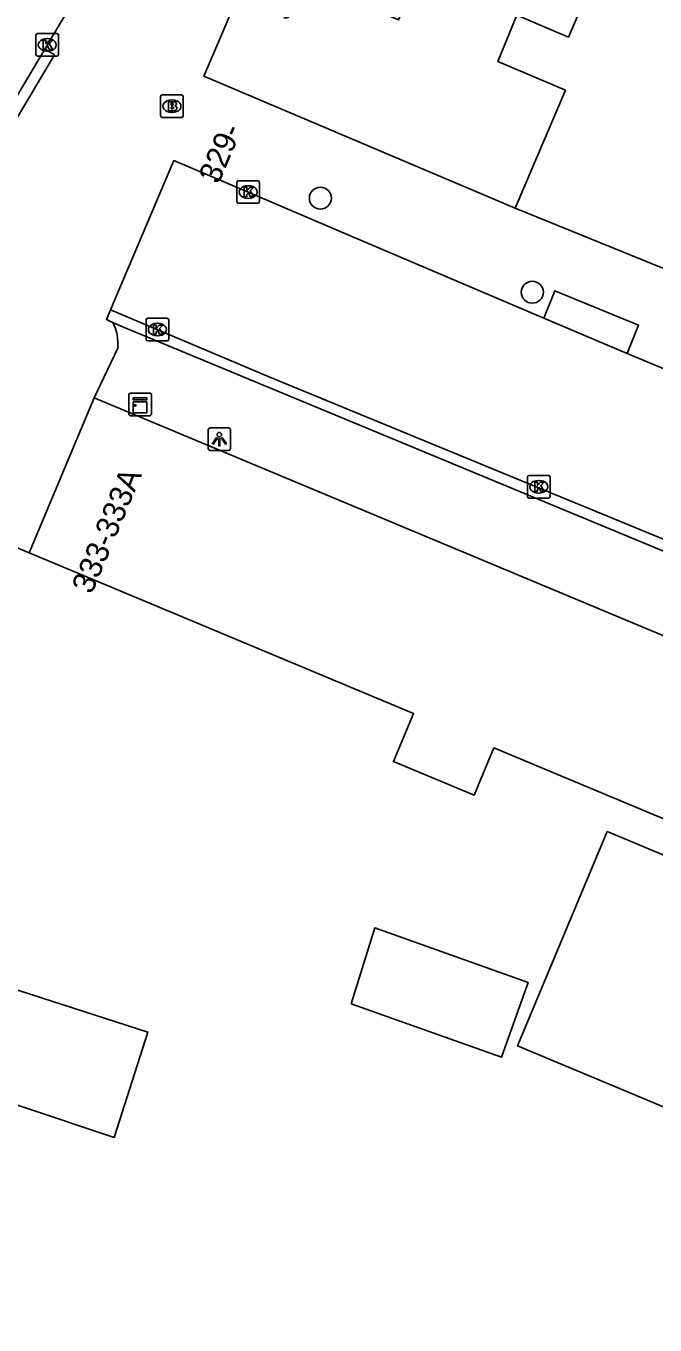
# Model space of a CAD drawing. Extents: x 160557 to 161245, y 385330 to 386505.
# Drawn here: x 160889.6 to 160917.5, y 385811 to 385868.6 of the extents above; entities that cross this region are included whole.
import ezdxf

# ---------------------------------------------------------------- set-up
doc = ezdxf.new("R2010")
doc.units = 0
for name, color, linetype in [('IMGEO_Boom', 7, 'Continuous'), ('IMGEO_Brandkraan', 7, 'Continuous'), ('IMGEO_Kast', 7, 'Continuous'), ('IMGEO_Kolk', 7, 'Continuous'), ('IMGEO_Lichtpunt', 7, 'Continuous'), ('IMGEO_Pand', 7, 'Continuous'), ('IMGEO_Pand_nummerreeks', 7, 'Continuous'), ('IMGEO_Rijbaan_lokaal_gesloten', 7, 'Continuous'), ('IMGEO_Rijbaan_lokaal_open', 7, 'Continuous'), ('IMGEO_Voetpad_open', 7, 'Continuous')]:
    doc.layers.add(name, color=color, linetype=linetype)

msp = doc.modelspace()

# ---------------------------------------------------------------- linework, layer by layer
at = {"layer": 'IMGEO_Boom'}
for centre in [(160902.686, 385860.988), (160912.08, 385856.817)]:
    msp.add_circle(centre, 0.489, dxfattribs=at)
at = {"layer": 'IMGEO_Brandkraan'}
for p, q in [((160895.602, 385864.643), (160895.602, 385865.495)), ((160895.677, 385865.569), (160896.529, 385865.569)), ((160896.603, 385865.495), (160896.603, 385864.643)), ((160896.09, 385865.349), (160896.115, 385865.349)), ((160896.529, 385864.569), (160895.677, 385864.569)), ((160896.113, 385864.789), (160896.088, 385864.789))]:
    msp.add_line(p, q, dxfattribs=at)
for points in [[(160895.602, 385864.643), (160895.602, 385865.495)], [(160895.677, 385865.569), (160896.529, 385865.569)], [(160896.603, 385865.495), (160896.603, 385864.643)], [(160895.95, 385865.269), (160895.95, 385864.869), (160896.163, 385864.869)], [(160896.181, 385865.269), (160895.95, 385865.269)], [(160896.129, 385865.188), (160896.075, 385865.188), (160896.075, 385865.112)], [(160896.075, 385865.112), (160896.128, 385865.112)], [(160896.137, 385865.036), (160896.075, 385865.036), (160896.075, 385864.955)], [(160896.075, 385864.955), (160896.137, 385864.955)], [(160896.529, 385864.569), (160895.677, 385864.569)]]:
    msp.add_lwpolyline(points, dxfattribs=at)
for centre, radius, start, end in [((160895.679, 385865.493), 0.0765, 91.55205, 178.44795), ((160895.679, 385865.493), 0.0765, 91.55205, 178.44795), ((160896.527, 385865.493), 0.0765, 1.55205, 88.44795), ((160896.527, 385865.493), 0.0765, 1.55205, 88.44795), ((160896.13, 385865.15), 0.0379, 267.82845, 90.93552), ((160896.138, 385864.995), 0.0404, 269.87594, 90.50774), ((160896.169, 385865.12), 0.251, 268.66757, 293.53466), ((160896.185, 385865.124), 0.145, 59.4692, 91.53667), ((160896.21, 385865.171), 0.0922, 285.51372, 58.15012), ((160896.215, 385864.979), 0.105, 301.31148, 78.98903), ((160895.679, 385864.645), 0.0765, 181.55205, 268.44795), ((160895.679, 385864.645), 0.0765, 181.55205, 268.44795), ((160896.527, 385864.645), 0.0765, 271.55205, 358.44795), ((160896.527, 385864.645), 0.0765, 271.55205, 358.44795)]:
    msp.add_arc(centre, radius, start, end, dxfattribs=at)
for centre, major_axis, ratio, start_param, end_param in [((160896.089, 385865.069), (-0.387, 0.002), 0.722429, 4.712389, 7.853982), ((160896.114, 385865.069), (-0.39, 0.002), 0.717154, 1.570796, 4.712389)]:
    msp.add_ellipse(centre, major_axis=major_axis, ratio=ratio, start_param=start_param, end_param=end_param, dxfattribs=at)
at = {"layer": 'IMGEO_Kast'}
for p, q in [((160894.194, 385851.411), (160894.194, 385852.252)), ((160894.194, 385852.252), (160894.194, 385851.411)), ((160894.269, 385852.336), (160895.11, 385852.336)), ((160895.11, 385852.336), (160894.269, 385852.336)), ((160895.194, 385852.261), (160895.194, 385851.42)), ((160895.194, 385851.42), (160895.194, 385852.261)), ((160895.119, 385851.336), (160894.278, 385851.336)), ((160894.278, 385851.336), (160895.119, 385851.336))]:
    msp.add_line(p, q, dxfattribs=at)
for points in [[(160894.389, 385852.126), (160894.989, 385852.126), (160894.989, 385852.041), (160894.389, 385852.041), (160894.389, 385852.126)], [(160894.389, 385851.951), (160894.989, 385851.951), (160894.989, 385851.462), (160894.389, 385851.462), (160894.389, 385851.951)]]:
    msp.add_lwpolyline(points, dxfattribs=at)
msp.add_circle((160894.473, 385851.8), 0.0377, dxfattribs=at)
for centre, start, end in [((160894.272, 385852.258), 92.4484, 184.28452), ((160894.272, 385852.258), 92.4484, 184.28452), ((160895.116, 385852.258), 2.4484, 94.28452), ((160895.116, 385852.258), 2.4484, 94.28452), ((160894.272, 385851.414), 182.4484, 274.28452), ((160894.272, 385851.414), 182.4484, 274.28452), ((160895.116, 385851.414), 272.4484, 4.28452), ((160895.116, 385851.414), 272.4484, 4.28452)]:
    msp.add_arc(centre, 0.0779, start, end, dxfattribs=at)
at = {"layer": 'IMGEO_Kolk'}
for p, q in [((160890.074, 385867.362), (160890.074, 385868.214)), ((160890.149, 385868.288), (160891.001, 385868.288)), ((160890.562, 385868.068), (160890.587, 385868.068)), ((160891.075, 385868.214), (160891.075, 385867.362)), ((160891.001, 385867.288), (160890.149, 385867.288)), ((160890.585, 385867.508), (160890.56, 385867.508)), ((160898.983, 385860.834), (160898.983, 385861.686)), ((160899.058, 385861.76), (160899.91, 385861.76)), ((160899.471, 385861.54), (160899.496, 385861.54)), ((160899.984, 385861.686), (160899.984, 385860.834)), ((160899.494, 385860.98), (160899.469, 385860.98)), ((160899.91, 385860.76), (160899.058, 385860.76)), ((160894.958, 385854.733), (160894.958, 385855.585)), ((160895.033, 385855.659), (160895.885, 385855.659)), ((160895.446, 385855.439), (160895.471, 385855.439)), ((160895.959, 385855.585), (160895.959, 385854.733)), ((160895.885, 385854.659), (160895.033, 385854.659)), ((160895.469, 385854.879), (160895.444, 385854.879)), ((160911.864, 385847.759), (160911.864, 385848.611)), ((160911.939, 385848.685), (160912.791, 385848.685)), ((160912.352, 385848.465), (160912.377, 385848.465)), ((160912.865, 385848.611), (160912.865, 385847.759)), ((160912.791, 385847.685), (160911.939, 385847.685)), ((160912.375, 385847.905), (160912.35, 385847.905))]:
    msp.add_line(p, q, dxfattribs=at)
for points in [[(160890.074, 385867.362), (160890.074, 385868.214)], [(160890.149, 385868.288), (160891.001, 385868.288)], [(160890.395, 385867.988), (160890.518, 385867.988), (160890.518, 385867.837), (160890.648, 385867.988), (160890.812, 385867.988), (160890.666, 385867.837), (160890.819, 385867.588), (160890.667, 385867.588), (160890.582, 385867.752), (160890.518, 385867.685), (160890.518, 385867.588), (160890.395, 385867.588), (160890.395, 385867.988)], [(160891.075, 385868.214), (160891.075, 385867.362)], [(160891.001, 385867.288), (160890.149, 385867.288)], [(160898.983, 385860.834), (160898.983, 385861.686)], [(160899.058, 385861.76), (160899.91, 385861.76)], [(160899.304, 385861.46), (160899.427, 385861.46), (160899.427, 385861.309), (160899.557, 385861.46), (160899.721, 385861.46), (160899.575, 385861.309), (160899.728, 385861.06), (160899.576, 385861.06), (160899.491, 385861.224), (160899.427, 385861.157), (160899.427, 385861.06), (160899.304, 385861.06), (160899.304, 385861.46)], [(160899.984, 385861.686), (160899.984, 385860.834)], [(160899.91, 385860.76), (160899.058, 385860.76)], [(160894.958, 385854.733), (160894.958, 385855.585)], [(160895.033, 385855.659), (160895.885, 385855.659)], [(160895.279, 385855.359), (160895.402, 385855.359), (160895.402, 385855.208), (160895.532, 385855.359), (160895.696, 385855.359), (160895.55, 385855.208), (160895.703, 385854.959), (160895.551, 385854.959), (160895.466, 385855.123), (160895.402, 385855.056), (160895.402, 385854.959), (160895.279, 385854.959), (160895.279, 385855.359)], [(160895.959, 385855.585), (160895.959, 385854.733)], [(160895.885, 385854.659), (160895.033, 385854.659)], [(160911.864, 385847.759), (160911.864, 385848.611)], [(160911.939, 385848.685), (160912.791, 385848.685)], [(160912.185, 385848.385), (160912.308, 385848.385), (160912.308, 385848.234), (160912.438, 385848.385), (160912.602, 385848.385), (160912.456, 385848.234), (160912.609, 385847.985), (160912.457, 385847.985), (160912.372, 385848.149), (160912.308, 385848.082), (160912.308, 385847.985), (160912.185, 385847.985), (160912.185, 385848.385)], [(160912.865, 385848.611), (160912.865, 385847.759)], [(160912.791, 385847.685), (160911.939, 385847.685)]]:
    msp.add_lwpolyline(points, dxfattribs=at)
for centre, start, end in [((160890.151, 385868.212), 91.55205, 178.44795), ((160890.151, 385868.212), 91.55205, 178.44795), ((160890.999, 385868.212), 1.55205, 88.44795), ((160890.999, 385868.212), 1.55205, 88.44795), ((160890.151, 385867.364), 181.55205, 268.44795), ((160890.151, 385867.364), 181.55205, 268.44795), ((160890.999, 385867.364), 271.55205, 358.44795), ((160890.999, 385867.364), 271.55205, 358.44795), ((160899.06, 385861.684), 91.55205, 178.44795), ((160899.06, 385861.684), 91.55205, 178.44795), ((160899.908, 385861.684), 1.55205, 88.44795), ((160899.908, 385861.684), 1.55205, 88.44795), ((160899.06, 385860.836), 181.55205, 268.44795), ((160899.06, 385860.836), 181.55205, 268.44795), ((160899.908, 385860.836), 271.55205, 358.44795), ((160899.908, 385860.836), 271.55205, 358.44795), ((160895.035, 385855.583), 91.55205, 178.44795), ((160895.035, 385855.583), 91.55205, 178.44795), ((160895.883, 385855.583), 1.55205, 88.44795), ((160895.883, 385855.583), 1.55205, 88.44795), ((160895.035, 385854.735), 181.55205, 268.44795), ((160895.035, 385854.735), 181.55205, 268.44795), ((160895.883, 385854.735), 271.55205, 358.44795), ((160895.883, 385854.735), 271.55205, 358.44795), ((160911.941, 385848.609), 91.55205, 178.44795), ((160911.941, 385848.609), 91.55205, 178.44795), ((160912.789, 385848.609), 1.55205, 88.44795), ((160912.789, 385848.609), 1.55205, 88.44795), ((160911.941, 385847.761), 181.55205, 268.44795), ((160911.941, 385847.761), 181.55205, 268.44795), ((160912.789, 385847.761), 271.55205, 358.44795), ((160912.789, 385847.761), 271.55205, 358.44795)]:
    msp.add_arc(centre, 0.0765, start, end, dxfattribs=at)
for centre, major_axis, ratio, start_param, end_param in [((160890.561, 385867.788), (-0.387, 0.002), 0.722429, 4.712389, 7.853982), ((160890.586, 385867.788), (-0.39, 0.002), 0.717154, 1.570796, 4.712389), ((160899.47, 385861.26), (-0.387, 0.002), 0.722429, 4.712389, 7.853982), ((160899.495, 385861.26), (-0.39, 0.002), 0.717154, 1.570796, 4.712389), ((160895.445, 385855.159), (-0.387, 0.002), 0.722429, 4.712389, 7.853982), ((160895.47, 385855.159), (-0.39, 0.002), 0.717154, 1.570796, 4.712389), ((160912.351, 385848.185), (-0.387, 0.002), 0.722429, 4.712389, 7.853982), ((160912.376, 385848.185), (-0.39, 0.002), 0.717154, 1.570796, 4.712389)]:
    msp.add_ellipse(centre, major_axis=major_axis, ratio=ratio, start_param=start_param, end_param=end_param, dxfattribs=at)
at = {"layer": 'IMGEO_Lichtpunt'}
for p, q in [((160897.707, 385850.7), (160897.707, 385849.893)), ((160897.707, 385850.7), (160897.707, 385849.893)), ((160898.609, 385850.795), (160897.801, 385850.795)), ((160898.609, 385850.795), (160897.801, 385850.795)), ((160898.703, 385849.893), (160898.703, 385850.7)), ((160898.703, 385849.893), (160898.703, 385850.7)), ((160897.801, 385849.799), (160898.609, 385849.799)), ((160897.801, 385849.799), (160898.609, 385849.799))]:
    msp.add_line(p, q, dxfattribs=at)
for points in [[(160898.081, 385850.364), (160898.12, 385850.336), (160897.932, 385850.074), (160897.894, 385850.101), (160898.081, 385850.364)], [(160898.183, 385850.316), (160898.23, 385850.316), (160898.23, 385849.994), (160898.183, 385849.994), (160898.183, 385850.316)], [(160898.293, 385850.336), (160898.331, 385850.363), (160898.518, 385850.101), (160898.479, 385850.073), (160898.293, 385850.336)]]:
    msp.add_lwpolyline(points, dxfattribs=at)
msp.add_circle((160898.206, 385850.498), 0.0994, dxfattribs=at)
for centre, start, end in [((160897.801, 385850.7), 90, 180), ((160897.801, 385850.7), 90, 180), ((160898.609, 385850.7), 0, 90), ((160898.609, 385850.7), 0, 90), ((160897.801, 385849.893), 180, 270), ((160897.801, 385849.893), 180, 270), ((160898.609, 385849.893), 270, 0), ((160898.609, 385849.893), 270, 360)]:
    msp.add_arc(centre, 0.0946, start, end, dxfattribs=at)
at = {"layer": 'IMGEO_Pand'}
for points in [[(160903.823, 385878.191), (160903.648, 385878.265), (160903.448, 385877.775), (160901.547, 385873.307), (160905.507, 385871.63), (160907.045, 385870.979), (160906.151, 385868.902), (160904.614, 385869.556), (160899.733, 385871.634), (160899.536, 385871.153), (160897.512, 385866.406), (160911.32, 385860.54)], [(160903.823, 385878.191), (160915.8, 385873.09), (160913.688, 385868.131), (160911.399, 385869.106), (160910.557, 385867.047), (160913.545, 385865.778), (160911.32, 385860.54)], [(160892.651, 385852.132), (160889.773, 385845.251)], [(160892.651, 385852.132), (160941.521, 385831.694), (160941.467, 385831.564)], [(160941.467, 385831.564), (160939.592, 385827.082), (160938.63, 385824.783), (160910.376, 385836.599), (160909.497, 385834.498), (160905.918, 385835.995), (160906.809, 385838.126), (160889.773, 385845.251)], [(160915.402, 385832.888), (160945.008, 385820.507), (160941.031, 385810.998), (160911.425, 385823.38), (160915.402, 385832.888)], [(160904.048, 385825.242), (160905.093, 385828.611), (160911.893, 385826.2), (160910.714, 385822.877), (160904.048, 385825.242)], [(160873.41, 385826.084), (160878.148, 385824.485), (160881.83, 385823.242), (160893.546, 385819.32), (160895.037, 385823.997), (160887.47, 385826.436)]]:
    msp.add_lwpolyline(points, dxfattribs=at)
at = {"layer": 'IMGEO_Rijbaan_lokaal_gesloten'}
for points in [[(160890.464, 385867.601), (160892.832, 385871.586)], [(160884.455, 385857.488), (160890.464, 385867.601)], [(160912.588, 385855.659), (160903.848, 385859.395), (160899.484, 385861.26), (160896.184, 385862.656), (160893.378, 385856.039)], [(160893.378, 385856.039), (160900.444, 385853.054), (160936.154, 385838.328), (160943.719, 385835.176), (160953.399, 385831.56)], [(160916.29, 385854.104), (160912.588, 385855.659)], [(160927.245, 385849.527), (160924.113, 385850.835), (160916.29, 385854.104)]]:
    msp.add_lwpolyline(points, dxfattribs=at)
at = {"layer": 'IMGEO_Rijbaan_lokaal_open'}
for points in [[(160893.378, 385856.039), (160893.195, 385855.607), (160893.326, 385855.547), (160893.484, 385855.474)], [(160943.83, 385834.567), (160893.952, 385855.26), (160893.513, 385855.461), (160893.484, 385855.474)]]:
    msp.add_lwpolyline(points, dxfattribs=at)
at = {"layer": 'IMGEO_Voetpad_open'}
for points in [[(160884.455, 385857.488), (160884.884, 385857.233), (160890.893, 385867.346), (160890.464, 385867.601)], [(160911.32, 385860.54), (160917.871, 385857.887)], [(160916.29, 385854.104), (160916.788, 385855.357), (160913.079, 385856.883), (160912.588, 385855.659)], [(160893.698, 385854.337), (160892.651, 385852.132)], [(160889.773, 385845.251), (160885.744, 385846.936)]]:
    msp.add_lwpolyline(points, dxfattribs=at)
msp.add_arc((160891.699, 385854.549), 2.01, 353.93573, 27.38268, dxfattribs=at)

# ---------------------------------------------------------------- texts
at = {"layer": 'IMGEO_Pand_nummerreeks'}
for s, rotation, p in [('329-              329L', 66.91001, (160898.169, 385861.574)), ('333-333A', 67.30273, (160892.547, 385843.383))]:
    msp.add_text(s, height=1, rotation=rotation, dxfattribs=at).set_placement(p)

doc.saveas('drawing.dxf')
